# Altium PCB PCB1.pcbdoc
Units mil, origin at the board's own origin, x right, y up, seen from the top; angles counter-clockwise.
Board outline 1496.06 x 3523.62 mil, 2 copper layers (Top Layer, Bottom Layer), stack 62.206 mil thick; 12 components, 18 nets, 70 pads, 9 vias.
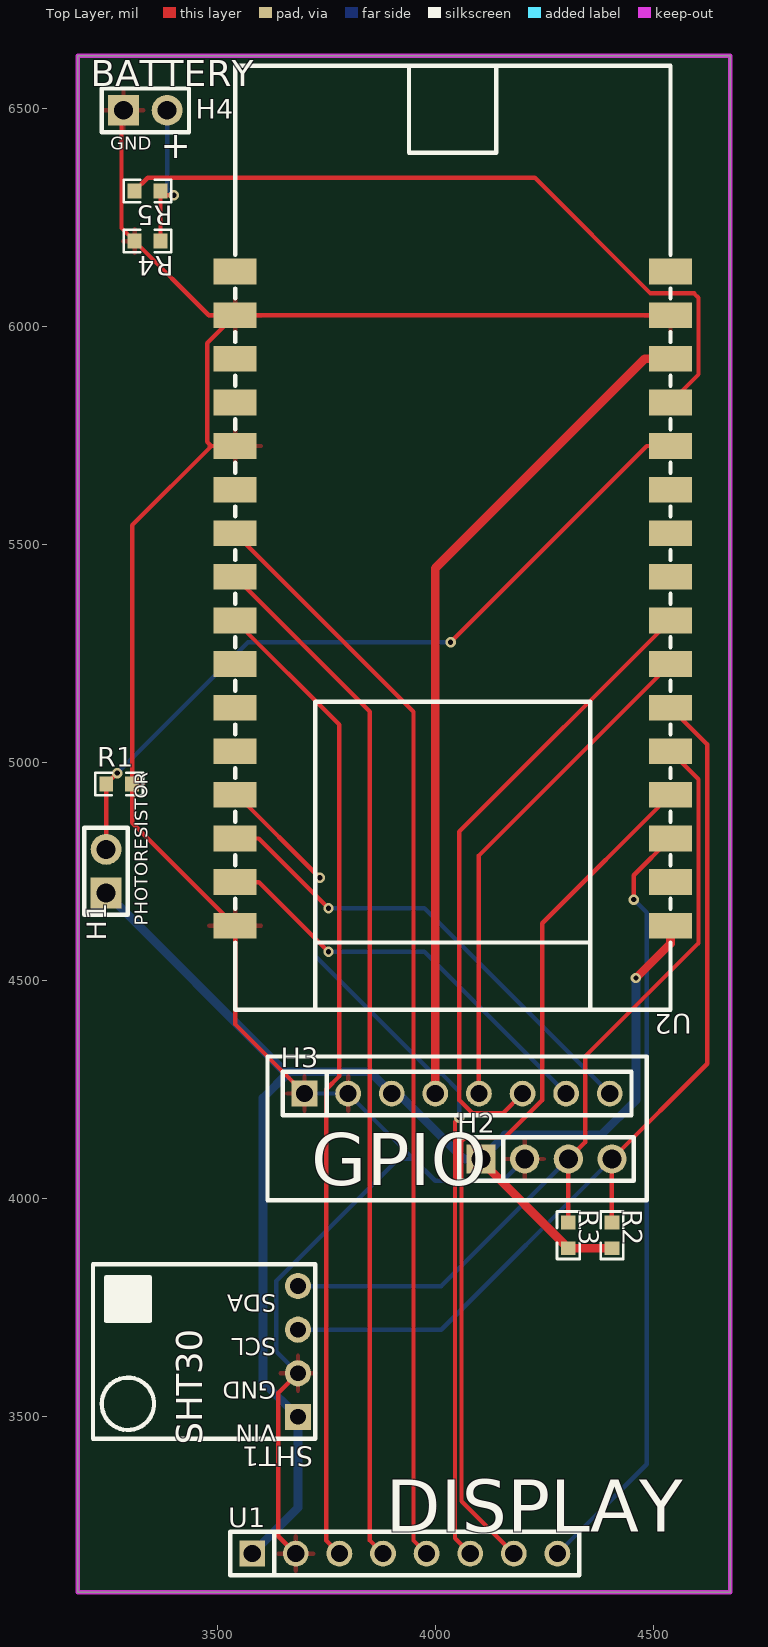
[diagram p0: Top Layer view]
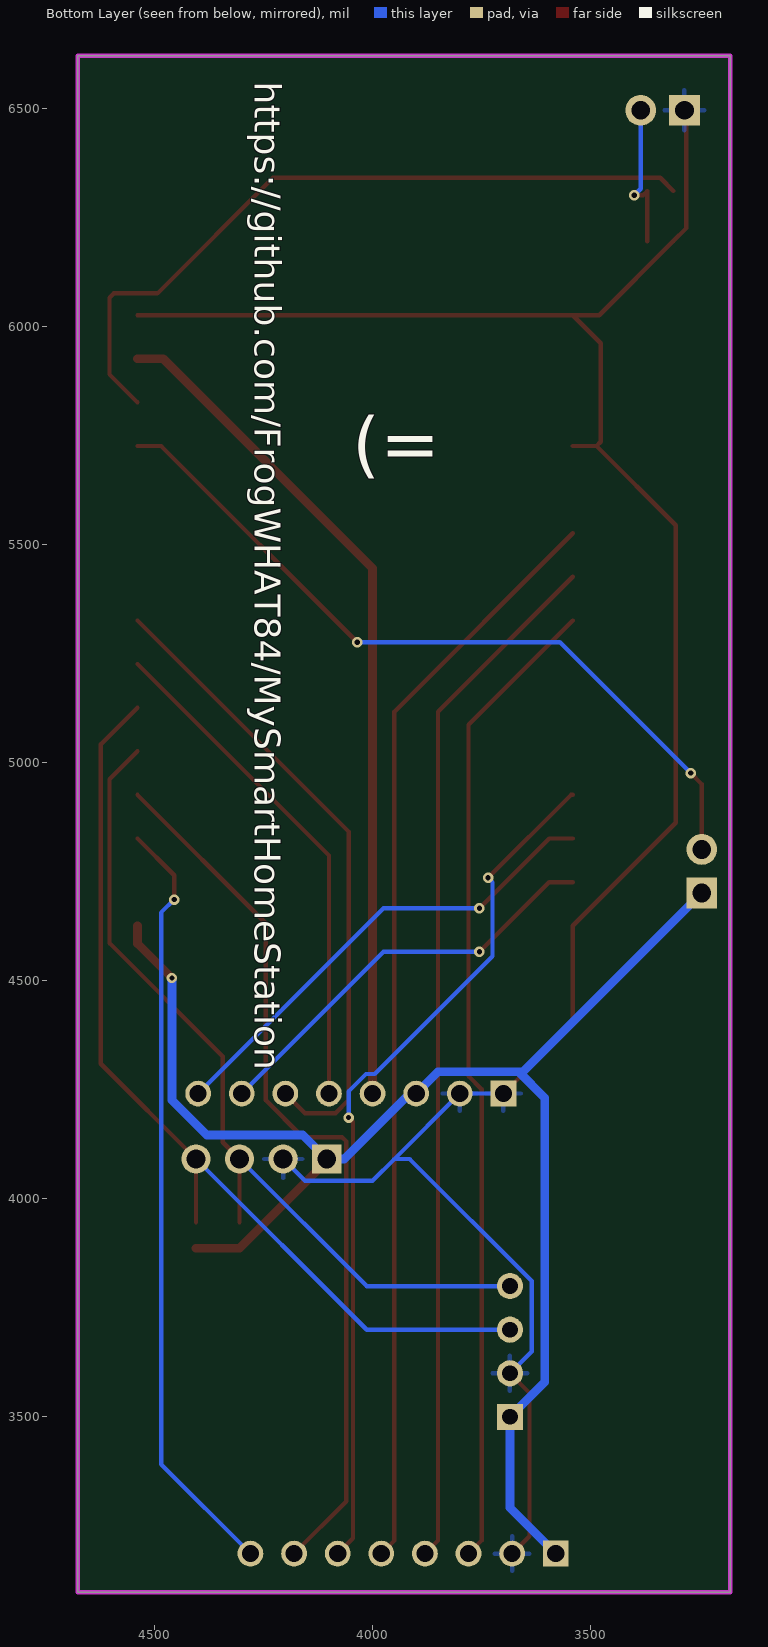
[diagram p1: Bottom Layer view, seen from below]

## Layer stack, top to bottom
Top Solder Mask Layer: solder mask 0.394, Dk 3.3
Top Layer: signal copper 1.379
Dielectric1: surface 59.449, FR4, Dk 4.5
Bottom Layer: signal copper 1.378
Bottom Solder Mask Layer: solder mask 0.394, Dk 3.3

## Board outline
3180,6620 3180,3096.38 4676.06,3096.38 4676.06,6620

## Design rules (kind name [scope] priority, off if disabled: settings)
BoardOutlineClearance copperThickness1oz [All] p0: genericclearance=10 ignorepadtopadclearanceinfootprint=FALSE except(0: Arc-SplitContinuation Track-SplitContinuation SMDPad-SplitContinuation THPad-SplitContinuation Via-SplitContinuation Fill-SplitContinuation Poly-SplitContinuation Region-SplitContinuation Text-SplitContinuation)
BoardOutlineClearance copperThickness2oz [All] p0: genericclearance=10 ignorepadtopadclearanceinfootprint=FALSE except(0: Arc-SplitContinuation Track-SplitContinuation SMDPad-SplitContinuation THPad-SplitContinuation Via-SplitContinuation Fill-SplitContinuation Poly-SplitContinuation Region-SplitContinuation Text-SplitContinuation)
BoardOutlineClearance otherClearance [All] p0: genericclearance=10 ignorepadtopadclearanceinfootprint=FALSE except(0: Arc-SplitContinuation Track-SplitContinuation SMDPad-SplitContinuation THPad-SplitContinuation Via-SplitContinuation Fill-SplitContinuation Poly-SplitContinuation Region-SplitContinuation Text-SplitContinuation)
Clearance copperThickness1oz [All] p1: gap=7 ignorepadtopadclearanceinfootprint=FALSE
Clearance copperThickness2oz [All] p1: gap=7 ignorepadtopadclearanceinfootprint=FALSE
Clearance otherClearance [All] p1: gap=7 ignorepadtopadclearanceinfootprint=FALSE
DiffPairsRouting differentialPair [All] p1: maxuncoupledlength=10 minlimit=6 maxlimit=Infinity mostfreqgap=6 toplayer_minwidth=5 toplayer_prefwidth=10 toplayer_maxwidth=100 bottomlayer_minwidth=5 bottomlayer_prefwidth=10 bottomlayer_maxwidth=100
PasteMaskExpansion pasteMaskExpansion [All] p1: expansion=0
PlaneConnect innerPlane [All] p1: planeconnectstyle=Relief reliefexpansion=20 reliefentries=4 reliefconductorwidth=10 reliefairgap=10
PolygonConnect copperRegion [All] p1: connectstyle=Relief reliefentries=4 reliefconductorwidth=10 polygonreliefangle="90 Angle" airgapwidth=10
RoutingVias viaSize [All] p1: viastyle="Through Hole" holewidth=12.0078 minholewidth=11.811 maxholewidth=248.0314 width=12.0078 minwidth=11.811 maxwidth=248.0314
SolderMaskExpansion solderMaskExpansion [IsVia] p1: useseparateexpansions=TRUE expansion=-1000 expansionbottom=-1000
SolderMaskExpansion solderMaskExpansion [All] p2: useseparateexpansions=TRUE expansion=2 expansionbottom=2
Width copperThickness1oz [All] p1: maxlimit=100 minlimit=5 preferedwidth=10
Width copperThickness2oz [All] p1: maxlimit=100 minlimit=8 preferedwidth=10
Width trackWidth1 [All] p1: maxlimit=100 minlimit=15 preferedwidth=20

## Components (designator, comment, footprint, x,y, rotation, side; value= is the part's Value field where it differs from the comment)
H1 "" HDR-TH_2P-P2.54-V-M-1 3245,4750 r90 top
H2 "" HDR-TH_4P-P2.54-V-M 4255,4090 r0 top
H3 "" HDR-TH_8P-P2.54-V-M 4050,4240 r0 top
H4 "" HDR-TH_2P-P2.54-V-M-1 3335,6495 r0 top
R1 "10K" R0603 3275,4950 r0 top
R2 "4.7K" R0603 4405,3915 r270 top
R3 "4.7K" R0603 4305,3915 r270 top
R4 "100K" R0603 3340,6195 r180 top
R5 "100K" R0603 3340,6310 r180 top
SHT1 "SHT30" SHT30 3685,3800 r180 top
U1 "YZT1069-06115-08025-01" HDR-TH_8P-P2.54-V-M 3930,3185 r0 top
U2 "ESP32-C6-DEV-KIT-N8" COMM-SMD_L55.0-W25.4_ESP32-C6-DEV-KIT-N8 4040,5375 r180 top

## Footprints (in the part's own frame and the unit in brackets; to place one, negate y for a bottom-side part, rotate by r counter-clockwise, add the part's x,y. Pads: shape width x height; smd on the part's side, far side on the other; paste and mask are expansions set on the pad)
COMM-SMD_L55.0-W25.4_ESP32-C6-DEV-KIT-N8 [mm]
  rect 2.5x1.5 smd: 1(-12.68,19.05) 2(-12.68,16.51) 3(-12.68,13.97) 4(-12.68,11.43) 5(-12.68,8.89) 6(-12.68,6.35) 7(-12.68,3.81) 8(-12.68,1.27) 9(-12.68,-1.27) 10(-12.68,-3.81) 11(-12.68,-6.35) 12(-12.68,-8.89) 13(-12.68,-11.43) 14(-12.68,-13.97) 15(-12.68,-16.51) 16(-12.68,-19.05) 17(12.68,-19.05) 18(12.68,-16.51) 19(12.68,-13.97) 20(12.68,-11.43) 21(12.68,-8.89) 22(12.68,-6.35) 23(12.68,-3.81) 24(12.68,-1.27) 25(12.68,1.27) 26(12.68,3.81) 27(12.68,6.35) 28(12.68,8.89) 29(12.68,11.43) 30(12.68,13.97) 31(12.68,16.51) 32(12.68,19.05)
  silkscreen extent -12.68,-31.05 12.68,23.95
HDR-TH_2P-P2.54-V-M-1 [mm]
  rect 1.8x1.8 hole 1.1: 1(-1.27,0)
  round 1.8 hole 1.1: 2(1.27,0)
  silkscreen extent -2.54,-1.27 2.54,1.27
HDR-TH_4P-P2.54-V-M [mm]
  rect 1.7x1.7 hole 1.1: 1(-3.81,0)
  round 1.7 hole 1.1: 2(-1.27,0) 3(1.27,0) 4(3.81,0)
  silkscreen extent -5.08,-1.27 5.08,1.27
HDR-TH_8P-P2.54-V-M [mm]
  rect 1.5x1.5 hole 1: 1(-8.89,0)
  round 1.5 hole 1: 2(-6.35,0) 3(-3.81,0) 4(-1.27,0) 5(1.27,0) 6(3.81,0) 7(6.35,0) 8(8.89,0)
  silkscreen extent -10.16,-1.27 10.16,1.27
R0603 [mil]
  rect 31.75x34.02 smd paste-3937.01 mask+2: 1(-29.66,0) 2(29.66,0)
  silkscreen extent -55,-26 55,26
SHT30 [mil]
  rect 60x60 hole 36 paste+0 mask+4: 1(0,301.5)
  round 60 hole 36 paste+0 mask+4: 2(0,201.5) 3(0,101.5) 4(0,1.5)
  silkscreen extent -40,-49 470,352

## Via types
v1: diameter 24.02, hole 12, Top Layer to Bottom Layer, 9 vias

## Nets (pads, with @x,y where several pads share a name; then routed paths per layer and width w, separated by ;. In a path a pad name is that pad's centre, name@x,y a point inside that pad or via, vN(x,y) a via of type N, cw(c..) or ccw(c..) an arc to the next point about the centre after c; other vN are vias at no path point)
3V3: H1.1 H2.1 H3.3 R2.2 R3.2 SHT1.1 U1.1 U2.1 | length 3550.4
  Top Layer w20: H2.1 4105,4085.34 R3.2 R2.2 ; v1(4460,4505) 4539.21,4584.22 U2.1
  Bottom Layer w20: H1.1 3655,4290 3665,4290 ; U1.1 3685,3290 SHT1.1 3605,3578.5 3605,4230 3665,4290 ; v1(4460,4505) 4460,4225 4380,4145 4160.01,4145 H2.1 4065,4090 3925,4230 3910,4230 3850,4290 3665,4290
5V: H3.4 U2.14 | length 1943
  Top Layer w20: H3.4 4000,5444.99 4480,5924.99 U2.14
$1N54: H4.2 R4.1 R5.1 | length 350.7
  Top Layer w10: R4.1 R5.1 3379.66,6300 v1(3400,6300)
  Bottom Layer w10: H4.2 3385,6315 v1(3400,6300)
BAT_ADC: R5.2 U2.13 | length 1686
  Top Layer w10: R5.2 3340.34,6340 4228.42,6340 4493.42,6074.99 4593.42,6074.99 4603.42,6064.99 4603.42,5889.21 U2.13
BUSY: U1.8 U2.3 | length 1772.2
  Top Layer w10: v1(4455,4685) 4455,4740.79 U2.3
  Bottom Layer w10: U1.8 4485,3390 4485,4655 v1(4455,4685)
CS: U1.5 U2.23 | length 2521.9
  Top Layer w10: U2.23 3950,5115.79 3950,3215 U1.5
DC: U1.6 U2.29 | length 1994.1
  Top Layer w10: U2.29 3545,4925 v1(3735,4735) ; v1(4055,4185) 4045,4175 4045,3220 U1.6
  Bottom Layer w10: v1(3735,4735) 3725,4725 3725,4555 3995,4285 4015,4285 4055,4245 v1(4055,4185)
DIN: U1.3 U2.25 | length 2263.9
  Top Layer w10: U2.25 3780,5085.79 3780,4280 3750,4250 3750,3215 U1.3
GND: H2.2 H3.1 H3.2 H4.1 R1.2 R4.2 SHT1.2 U1.2 U2.15 U2.18 U2.21 U2.32 | length 5443.2
  Top Layer w10: H4.1 3280.34,6490.34 3280.34,6225 R4.2 3480.35,6024.99 U2.18 ; U2.21 3486.57,5724.99 ; U1.2 3640,3225 3640,3553.5 SHT1.2 ; H3.1 3540.79,4399.21 U2.32 3304.66,4861.13 R1.2 3304.66,5543.08 3486.57,5724.99 ; U2.15 U2.18 ; 3486.57,5724.99 3476.57,5734.99 3476.57,5960.78 U2.18
  Bottom Layer w10: SHT1.2 3635,3648.5 3635,3810 3915,4090 3950,4090 ; H3.1 H3.2 3950,4090 ; H2.2 4155,4040 4000,4040 3950,4090
GPIO0: H3.5 U2.7 | length 1166.9
  Top Layer w10: H3.5 4100,4785.79 U2.7
GPIO1: H3.6 U2.8 | length 1476.6
  Top Layer w10: H3.6 4154.97,4195 4085,4195 4055,4225 4055,4840.79 U2.8
GPIO2: H1.2 R1.1 U2.12 | length 1765
  Top Layer w10: H1.2 3245.34,4800.34 R1.1 v1(3270.33,4975) ; v1(4035,5274.99) 4485,5724.99 U2.12
  Bottom Layer w10: v1(3270.33,4975) 3570.33,5274.99 v1(4035,5274.99)
RST: U1.7 U2.4 | length 2040.9
  Top Layer w10: U1.7 4060,3305 4060,4130.01 4070,4140.01 4160,4140.01 4245,4225 4245,4630.79 U2.4
RX: H3.8 U2.30 | length 1101.5
  Top Layer w10: U2.30 3595,4825 v1(3755,4665)
  Bottom Layer w10: v1(3755,4665) 3974.99,4665 H3.8
SCL: H2.4 R2.1 SHT1.3 U2.6 | length 2187.9
  Top Layer w10: R2.1 H2.4 4623.42,4308.42 4623.42,5040.79 U2.6
  Bottom Layer w10: SHT1.3 4013.5,3698.5 H2.4
SCLK: U1.4 U2.24 | length 2380.5
  Top Layer w10: U2.24 3850,5115.79 3850,3215 U1.4
SDA: H2.3 R3.1 SHT1.4 U2.5 | length 1971.3
  Top Layer w10: R3.1 H2.3 4343.42,4128.42 4343.42,4325 4603.42,4585 4603.42,4960.79 U2.5
  Bottom Layer w10: SHT1.4 4013.5,3798.5 H2.3
TX: H3.7 U2.31 | length 960.1
  Top Layer w10: U2.31 3595,4725 v1(3755,4565)
  Bottom Layer w10: v1(3755,4565) 3974.99,4565 H3.7
pads on no net: U2.2 U2.9 U2.10 U2.11 U2.16 U2.17 U2.19 U2.20 U2.22 U2.26 U2.27 U2.28

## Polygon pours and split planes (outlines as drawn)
GND on Top Layer (solid, pour order 0): 3000,6765 3000,3000 4765,3000 4765,6765
GND on Bottom Layer (solid, pour order 2): 3055,6815 3055,3020 4755,3020 4755,6815

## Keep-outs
Board Outline Layer:
  the board outline again, w10

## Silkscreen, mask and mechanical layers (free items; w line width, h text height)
Top Silkscreen Layer:
  lines w10: 3615,3995 3615,4325 4485,4325 4485,3995 3615,3995
  text "BATTERY" at 3210,6550 h60
  text "GND" at 3255,6405 h30
  text "+" at 3370,6385 h60
  text "PHOTORESISTOR" at 3340,4625 h30 r90
  text "GPIO" at 3715,4030 h120
  text "DISPLAY" at 3886.15,3235 h120
Bottom Silkscreen Layer:
  text "https://github.com/FrogWHAT84/MySmartHomeStation" at 4270,6560 h60 r90
  text "=)" at 3845,5775 h120 r180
